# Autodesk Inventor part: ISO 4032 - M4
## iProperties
Library Location: C:\Program Files\Autodesk\Inventor 6\content
Library: local
SubLibrary: ISO
Family: 51
Member: 60
Member Major Revision: 1
Member Minor Revision: 1
Comments: To add or edit properties for Autodesk Inventor files, use iProperties.
Created: 2003-05
Part Number: ISO 4032 - M4
Vendor: Autodesk Inc.
Document SubType Name: Modeling
Designer: Philippe
Description: Ecrou hexagonal
Standard: ISO 4032 M4
Alert: To add or edit properties for Autodesk Inventor files, use iProperties.
Control State: 0
Master: False
Checked Out: False
Shininess: 64.0
Length Units: 11269
Angle Units: 11279
Time Units: 11290
Mass Units: 11283
Length Display Precision: 3
Angle Display Precision: 2
Compacted: True
EGR: 1
Density: 0.0
Volumn: 0.0
Area: 0.0
PropertySet Name: Model Information
Author: Philippe
Revision Number: 1
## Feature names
1. Corps [Extrusion]
2. Chanfrein1 [Revolution]
3. Filetage [Hole]
4. Chanfrein2 [Chamfer]
5. Chanfrein3 [Chamfer]
